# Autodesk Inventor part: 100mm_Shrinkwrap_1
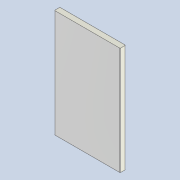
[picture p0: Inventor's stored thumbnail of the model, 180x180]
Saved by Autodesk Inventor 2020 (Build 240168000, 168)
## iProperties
Created: 2020-11
Part Number: 100mm_Shrinkwrap_1
Material: Generic
Document SubType Name: Modeling
Designer: Yolande
Density: 1 g/cm^3
Appearance: Default
Author: Yolande
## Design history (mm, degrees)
derived "100mm.iam"
body "Solid1"
node "Lambdaboard 100mm Mineral White.ipt:1" dims "d0" = 10
